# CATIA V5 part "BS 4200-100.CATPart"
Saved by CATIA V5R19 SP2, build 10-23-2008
Part number: BS 4200-100
Bounding box of the stored display mesh (mm): x -47.487 to 47.487, y -47.487 to 47.487, z 0 to 265
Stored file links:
  C:\Users\Bora\Desktop\3D Katı model\BS serisi\BS 4200\BS 4200-100.CATPart
  C:\Program Files\Dassault Systemes\B19\intel_a\reffiles\standard\MetricThickPitch.txt
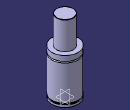
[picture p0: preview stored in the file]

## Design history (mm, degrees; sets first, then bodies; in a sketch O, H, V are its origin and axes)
Body1 (main body)
  Sketch1 on yz-plane, origin (0, 0, 0), H (0, 1, 0), V (0, 0, 1)
    point P2 (47.5, 140.5)
    point P5 (30, 264)
    point P7 (30, 264)
    point P11 (47.5, 145.5)
    point P13 (47.5, 145.5)
    point P14 (47.5, 140.5)
    line L1 (47.5, 13) -> (47.5, 140.5)
    line L2 (44.5, 13) -> (44.5, 8)
    line L3 (30, 264) -> (30, 164)
    arc A1 centre (29, 264) radius 1 from (30, 264) to (29, 265) ccw
    line L4 (47.5, 0) -> (47.5, 8)
    line L5 (47.5, 145.5) -> (47.5, 164)
    arc A2 centre (47.5, 143) radius 2.5 from (47.5, 145.5) to (47.5, 140.5) ccw
    line L6 (29, 265) -> (0, 265)
    point P15 (0, 265)
    line L7 (30, 164) -> (47.5, 164)
    line L8 (0, 0) -> (47.5, 0)
    line L9 (44.5, 13) -> (47.5, 13)
    line L10 (44.5, 8) -> (47.5, 8)
    coincidence: P15 V, P2 P14, P5 P7, P11 P13
    tangency: L6 A1
    horizontal: L7 H, L8 H, L9 H, L10 H
  Shaft1: profile Sketch1, axis Sketch1.V, angle 360
  Sketch2 on face of Shaft1 from Sketch1.L8, origin (0, 0, 0), H (1, 0, 0), V (0, -1, 0)
    point P1 (30, 0)
    distance P1 V = 30
  Hole1: placed by Sketch2, at (30, 0, 0) direction (0, 0, 1), diameter 6.647, depth 7, threaded "M8", thread diameter 8, thread depth 7, pitch 1.25
  CircPattern1: of Hole1, instances 4, angular step 90, axis from xy-plane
